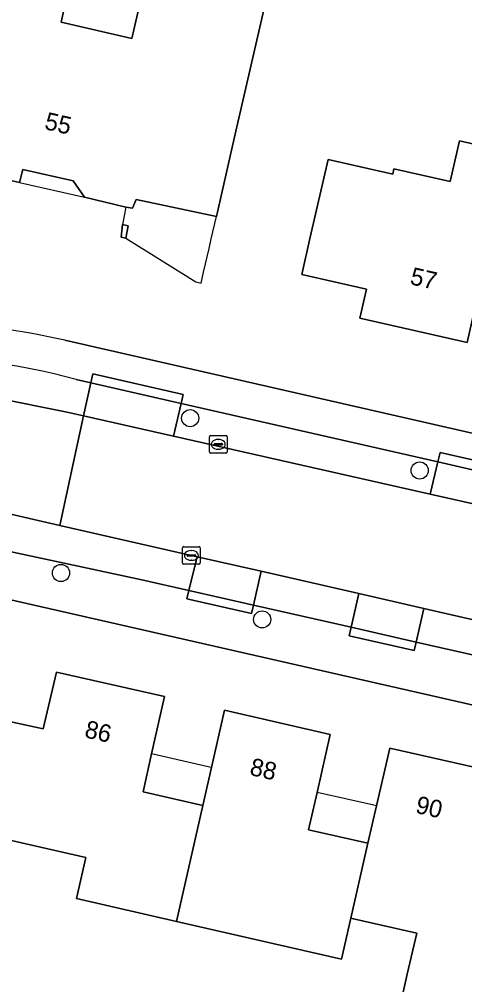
# Model space of a CAD drawing. Extents: x 159626 to 160723, y 388173 to 389416.
# Drawn here: x 160184.1 to 160209.5, y 388707.3 to 388762.4 of the extents above; entities that cross this region are included whole.
import ezdxf

# ---------------------------------------------------------------- set-up
doc = ezdxf.new("R2010")
doc.units = 0
for name, color, linetype in [('IMGEO_Boom', 7, 'Continuous'), ('IMGEO_Erf', 7, 'Continuous'), ('IMGEO_Kolk', 7, 'Continuous'), ('IMGEO_Pand', 7, 'Continuous'), ('IMGEO_Pand_nummerreeks', 7, 'Continuous'), ('IMGEO_Pand_overbouw', 7, 'Continuous'), ('IMGEO_Parkeervlak_open', 7, 'Continuous'), ('IMGEO_Rijbaan_lokaal_gesloten', 7, 'Continuous'), ('IMGEO_Voetpad_open', 7, 'Continuous')]:
    doc.layers.add(name, color=color, linetype=linetype)

msp = doc.modelspace()

# ---------------------------------------------------------------- linework, layer by layer
at = {"layer": 'IMGEO_Boom'}
for centre in [(160193.832, 388739.655), (160206.945, 388736.662), (160186.449, 388730.81), (160197.945, 388728.157)]:
    msp.add_circle(centre, 0.489, dxfattribs=at)
at = {"layer": 'IMGEO_Erf'}
for points in [[(160180.46, 388760.11), (160180.05, 388760.24), (160181.075, 388764.695), (160186.717, 388763.397), (160186.459, 388762.278), (160190.506, 388761.347), (160193.144, 388772.816), (160199.948, 388771.25), (160196.448, 388756.04), (160195.327, 388751.167), (160190.749, 388752.143), (160190.537, 388751.642), (160190.157, 388751.707), (160187.8, 388752.276), (160187.146, 388753.209), (160184.273, 388753.861), (160184.077, 388753.118), (160179.142, 388754.228)], [(160201.708, 388754.434), (160205.402, 388753.588), (160205.473, 388753.899), (160208.679, 388753.166), (160209.212, 388755.497), (160215.042, 388754.164), (160214.165, 388750.227), (160211.235, 388750.923), (160210.6, 388748.099), (160209.665, 388743.979), (160203.522, 388745.371), (160203.899, 388747.019), (160200.205, 388747.865), (160200.693, 388750)], [(160189.974, 388750.724), (160190.284, 388750.647), (160190.151, 388749.937), (160189.897, 388750)]]:
    msp.add_lwpolyline(points, close=True, dxfattribs=at)
for points in [[(160186.662, 388744.107), (160232.634, 388733.614)], [(160223.367, 388703.114), (160224.3, 388707.209), (160227.072, 388719.379), (160183.407, 388729.319), (160181.681, 388729.655), (160179.863, 388729.928)], [(160179.715, 388723.147), (160185.44, 388721.912), (160186.192, 388725.152), (160192.371, 388723.746), (160191.631, 388720.475), (160191.14, 388718.305), (160194.551, 388717.534), (160195.043, 388719.703), (160195.784, 388722.971), (160201.834, 388721.584), (160201.086, 388718.276), (160200.601, 388716.134), (160203.99, 388715.368), (160204.479, 388717.507), (160205.232, 388720.803), (160211.309, 388719.424)], [(160205.731, 388705.666), (160206.239, 388707.888), (160206.774, 388710.226), (160203.159, 388711.052), (160203.012, 388711.086), (160202.478, 388708.747), (160193.047, 388710.904), (160187.329, 388712.212), (160187.863, 388714.55), (160181.336, 388716.043)]]:
    msp.add_lwpolyline(points, dxfattribs=at)
msp.add_arc((160177.389, 388703.299), 41.849, 77.1976, 87.5469, dxfattribs=at)
at = {"layer": 'IMGEO_Kolk'}
for p, q in [((160194.938, 388737.735), (160194.938, 388738.587)), ((160195.013, 388738.661), (160195.865, 388738.661)), ((160195.939, 388738.587), (160195.939, 388737.735)), ((160195.197, 388738.155), (160195.197, 388738.167)), ((160195.635, 388738.118), (160195.237, 388738.118)), ((160195.24, 388738.204), (160195.638, 388738.204)), ((160195.426, 388738.441), (160195.451, 388738.441)), ((160195.681, 388738.167), (160195.681, 388738.155)), ((160195.865, 388737.661), (160195.013, 388737.661)), ((160195.449, 388737.881), (160195.424, 388737.881)), ((160193.399, 388731.387), (160193.399, 388732.239)), ((160193.474, 388732.313), (160194.326, 388732.313)), ((160193.887, 388732.093), (160193.912, 388732.093)), ((160194.4, 388732.239), (160194.4, 388731.387)), ((160193.658, 388731.807), (160193.658, 388731.819)), ((160194.096, 388731.77), (160193.698, 388731.77)), ((160193.701, 388731.856), (160194.099, 388731.856)), ((160193.91, 388731.533), (160193.885, 388731.533)), ((160194.142, 388731.819), (160194.142, 388731.807)), ((160194.326, 388731.313), (160193.474, 388731.313))]:
    msp.add_line(p, q, dxfattribs=at)
for points in [[(160194.938, 388737.735), (160194.938, 388738.587)], [(160195.013, 388738.661), (160195.865, 388738.661)], [(160195.939, 388738.587), (160195.939, 388737.735)], [(160195.865, 388737.661), (160195.013, 388737.661)], [(160193.399, 388731.387), (160193.399, 388732.239)], [(160193.474, 388732.313), (160194.326, 388732.313)], [(160194.4, 388732.239), (160194.4, 388731.387)], [(160194.326, 388731.313), (160193.474, 388731.313)]]:
    msp.add_lwpolyline(points, dxfattribs=at)
for centre, radius, start, end in [((160195.015, 388738.585), 0.0765, 91.552, 178.448), ((160195.015, 388738.585), 0.0765, 91.552, 178.448), ((160195.863, 388738.585), 0.0765, 1.552, 88.448), ((160195.863, 388738.585), 0.0765, 1.552, 88.448), ((160195.237, 388738.164), 0.0403, 85.8775, 175.7526), ((160195.234, 388738.154), 0.0366, 178.938, 274.7102), ((160195.638, 388738.161), 0.043, 264.8664, 352.4533), ((160195.642, 388738.166), 0.0386, 1.7309, 96.639), ((160195.015, 388737.737), 0.0765, 181.552, 268.448), ((160195.015, 388737.737), 0.0765, 181.552, 268.448), ((160195.863, 388737.737), 0.0765, 271.552, 358.448), ((160195.863, 388737.737), 0.0765, 271.552, 358.448), ((160193.476, 388732.237), 0.0765, 91.552, 178.448), ((160193.476, 388732.237), 0.0765, 91.552, 178.448), ((160194.324, 388732.237), 0.0765, 1.552, 88.448), ((160194.324, 388732.237), 0.0765, 1.552, 88.448), ((160193.476, 388731.389), 0.0765, 181.552, 268.448), ((160193.476, 388731.389), 0.0765, 181.552, 268.448), ((160193.698, 388731.816), 0.0403, 85.8775, 175.7526), ((160193.695, 388731.806), 0.0366, 178.938, 274.7102), ((160194.099, 388731.813), 0.043, 264.8664, 352.4533), ((160194.103, 388731.818), 0.0386, 1.7309, 96.639), ((160194.324, 388731.389), 0.0765, 271.552, 358.448), ((160194.324, 388731.389), 0.0765, 271.552, 358.448)]:
    msp.add_arc(centre, radius, start, end, dxfattribs=at)
for centre, major_axis, ratio, start_param, end_param in [((160195.425, 388738.161), (-0.387, 0.002), 0.722429, 4.712389, 7.853982), ((160195.45, 388738.161), (-0.39, 0.002), 0.717154, 1.570796, 4.712389), ((160193.886, 388731.813), (-0.387, 0.002), 0.722429, 4.712389, 7.853982), ((160193.911, 388731.813), (-0.39, 0.002), 0.717154, 1.570796, 4.712389)]:
    msp.add_ellipse(centre, major_axis=major_axis, ratio=ratio, start_param=start_param, end_param=end_param, dxfattribs=at)
at = {"layer": 'IMGEO_Pand'}
for points in [[(160195.327, 388751.167), (160196.448, 388756.04), (160199.948, 388771.25), (160193.144, 388772.816), (160190.506, 388761.347), (160186.459, 388762.278), (160186.717, 388763.397), (160181.075, 388764.695), (160180.05, 388760.24), (160180.46, 388760.11), (160179.142, 388754.228), (160184.077, 388753.118), (160184.273, 388753.861), (160187.146, 388753.209), (160187.8, 388752.276), (160190.157, 388751.707), (160190.537, 388751.642), (160190.749, 388752.143)], [(160214.165, 388750.227), (160215.042, 388754.164), (160209.212, 388755.497), (160208.679, 388753.166), (160205.473, 388753.899), (160205.402, 388753.588), (160201.708, 388754.434), (160200.693, 388750), (160200.205, 388747.865), (160203.899, 388747.019), (160203.522, 388745.371), (160209.665, 388743.979), (160210.6, 388748.099), (160211.235, 388750.923)], [(160189.974, 388750.724), (160189.897, 388750), (160190.151, 388749.937), (160190.284, 388750.647)], [(160191.631, 388720.475), (160192.371, 388723.746), (160186.192, 388725.152), (160185.44, 388721.912), (160179.715, 388723.147), (160181.336, 388716.043), (160187.863, 388714.55), (160187.329, 388712.212), (160193.047, 388710.904), (160194.551, 388717.534), (160191.14, 388718.305)], [(160201.086, 388718.276), (160201.834, 388721.584), (160195.784, 388722.971), (160195.043, 388719.703), (160194.551, 388717.534), (160193.047, 388710.904), (160202.478, 388708.747), (160203.012, 388711.086), (160203.99, 388715.368), (160200.601, 388716.134)], [(160213.45, 388713.222), (160210.078, 388713.984), (160210.553, 388716.084), (160211.309, 388719.424), (160205.232, 388720.803), (160204.479, 388717.507), (160203.99, 388715.368), (160203.012, 388711.086), (160203.159, 388711.052), (160206.774, 388710.226), (160206.239, 388707.888), (160205.731, 388705.666), (160208.592, 388701.238), (160208.943, 388701.124), (160209.218, 388702.195), (160210.98, 388701.792), (160211.459, 388703.887), (160212.026, 388706.564), (160211.928, 388706.586)]]:
    msp.add_lwpolyline(points, close=True, dxfattribs=at)
at = {"layer": 'IMGEO_Pand_overbouw'}
for points in [[(160187.8, 388752.276), (160187.146, 388753.209), (160184.273, 388753.861), (160184.077, 388753.118)], [(160189.974, 388750.724), (160190.284, 388750.647), (160190.151, 388749.937), (160194.153, 388747.437), (160194.453, 388747.373), (160194.596, 388747.991), (160194.91, 388749.355), (160195.033, 388749.891), (160195.327, 388751.167), (160190.749, 388752.143), (160190.537, 388751.642), (160190.157, 388751.707)], [(160195.043, 388719.703), (160194.865, 388719.743), (160191.631, 388720.475), (160191.14, 388718.305), (160194.551, 388717.534)], [(160204.479, 388717.507), (160204.319, 388717.543), (160201.086, 388718.276), (160200.601, 388716.134), (160203.99, 388715.368)]]:
    msp.add_lwpolyline(points, close=True, dxfattribs=at)
at = {"layer": 'IMGEO_Parkeervlak_open'}
for points in [[(160182.708, 388740.822), (160186.699, 388740.022), (160187.729, 388739.79), (160188.156, 388741.666), (160187.322, 388741.856)], [(160186.385, 388733.53), (160182.816, 388734.344)], [(160181.115, 388732.553), (160191.078, 388730.424), (160193.754, 388729.817), (160194.236, 388731.738), (160186.385, 388733.53)]]:
    msp.add_lwpolyline(points, dxfattribs=at)
for points in [[(160193.311, 388740.493), (160188.156, 388741.666), (160187.729, 388739.79), (160192.873, 388738.63)], [(160193.311, 388740.493), (160192.873, 388738.63), (160207.553, 388735.321), (160207.987, 388737.153)], [(160211.696, 388736.31), (160207.987, 388737.153), (160207.553, 388735.321), (160211.28, 388734.481)], [(160197.887, 388730.906), (160194.236, 388731.738), (160193.754, 388729.817), (160197.447, 388728.98)], [(160203.464, 388729.635), (160197.887, 388730.906), (160197.447, 388728.98), (160203.025, 388727.71)], [(160207.181, 388728.788), (160203.464, 388729.635), (160203.025, 388727.71), (160206.742, 388726.865)], [(160212.768, 388727.514), (160207.181, 388728.788), (160206.742, 388726.865), (160212.324, 388725.595)]]:
    msp.add_lwpolyline(points, close=True, dxfattribs=at)
msp.add_arc((160179.479, 388714.852), 28.12, 73.8041, 96.4315, dxfattribs=at)
at = {"layer": 'IMGEO_Rijbaan_lokaal_gesloten'}
for points in [[(160187.729, 388739.79), (160186.699, 388740.022), (160182.708, 388740.822)], [(160182.816, 388734.344), (160186.385, 388733.53), (160187.729, 388739.79)], [(160244.089, 388727.051), (160231.719, 388729.878), (160230.065, 388730.247), (160211.28, 388734.481), (160207.553, 388735.321), (160192.873, 388738.63), (160187.729, 388739.79), (160186.385, 388733.53), (160194.236, 388731.738), (160197.887, 388730.906), (160203.464, 388729.635), (160207.181, 388728.788), (160212.768, 388727.514), (160216.45, 388726.674), (160221.807, 388725.453), (160225.52, 388724.606), (160228.297, 388723.973), (160229.021, 388723.807), (160231.462, 388723.248), (160247.241, 388719.647)]]:
    msp.add_lwpolyline(points, dxfattribs=at)
at = {"layer": 'IMGEO_Voetpad_open'}
for points in [[(160232.634, 388733.614), (160186.662, 388744.107)], [(160187.322, 388741.856), (160188.156, 388741.666), (160188.276, 388742.193), (160193.434, 388741.012), (160193.311, 388740.493), (160207.987, 388737.153), (160208.117, 388737.698), (160211.81, 388736.85), (160211.696, 388736.31), (160227.347, 388732.748)], [(160225.081, 388722.687), (160224.97, 388722.2), (160221.258, 388723.045), (160221.37, 388723.533), (160216.013, 388724.754), (160215.9, 388724.267), (160212.213, 388725.108), (160212.324, 388725.595), (160206.742, 388726.865), (160206.631, 388726.377), (160202.914, 388727.223), (160203.025, 388727.71), (160197.447, 388728.98), (160197.336, 388728.492), (160193.643, 388729.33), (160193.754, 388729.817), (160191.078, 388730.424), (160181.115, 388732.553)], [(160174.144, 388731.086), (160179.863, 388729.928), (160181.681, 388729.655), (160183.407, 388729.319), (160227.072, 388719.379), (160229.749, 388718.77), (160237.27, 388717.058), (160321.781, 388697.748), (160325.989, 388696.807)]]:
    msp.add_lwpolyline(points, dxfattribs=at)
for points in [[(160188.156, 388741.666), (160193.311, 388740.493), (160193.434, 388741.012), (160188.276, 388742.193)], [(160211.696, 388736.31), (160211.81, 388736.85), (160208.117, 388737.698), (160207.987, 388737.153)], [(160193.754, 388729.817), (160193.643, 388729.33), (160197.336, 388728.492), (160197.447, 388728.98)], [(160203.025, 388727.71), (160202.914, 388727.223), (160206.631, 388726.377), (160206.742, 388726.865)]]:
    msp.add_lwpolyline(points, close=True, dxfattribs=at)
for centre, radius, start, end in [((160177.389, 388703.299), 41.849, 77.1976, 87.5469), ((160179.479, 388714.852), 28.12, 73.8041, 96.4315)]:
    msp.add_arc(centre, radius, start, end, dxfattribs=at)

# ---------------------------------------------------------------- texts
at = {"layer": 'IMGEO_Pand_nummerreeks'}
for s, rotation, p in [('55', 347.2138, (160185.461, 388756.175)), ('57', 347.2345, (160206.344, 388747.314)), ('86', 347.1829, (160187.748, 388721.434)), ('88', 347.0913, (160197.184, 388719.285)), ('90', 347.2116, (160206.658, 388717.116))]:
    msp.add_text(s, height=1, rotation=rotation, dxfattribs=at).set_placement(p)

doc.saveas('drawing.dxf')
